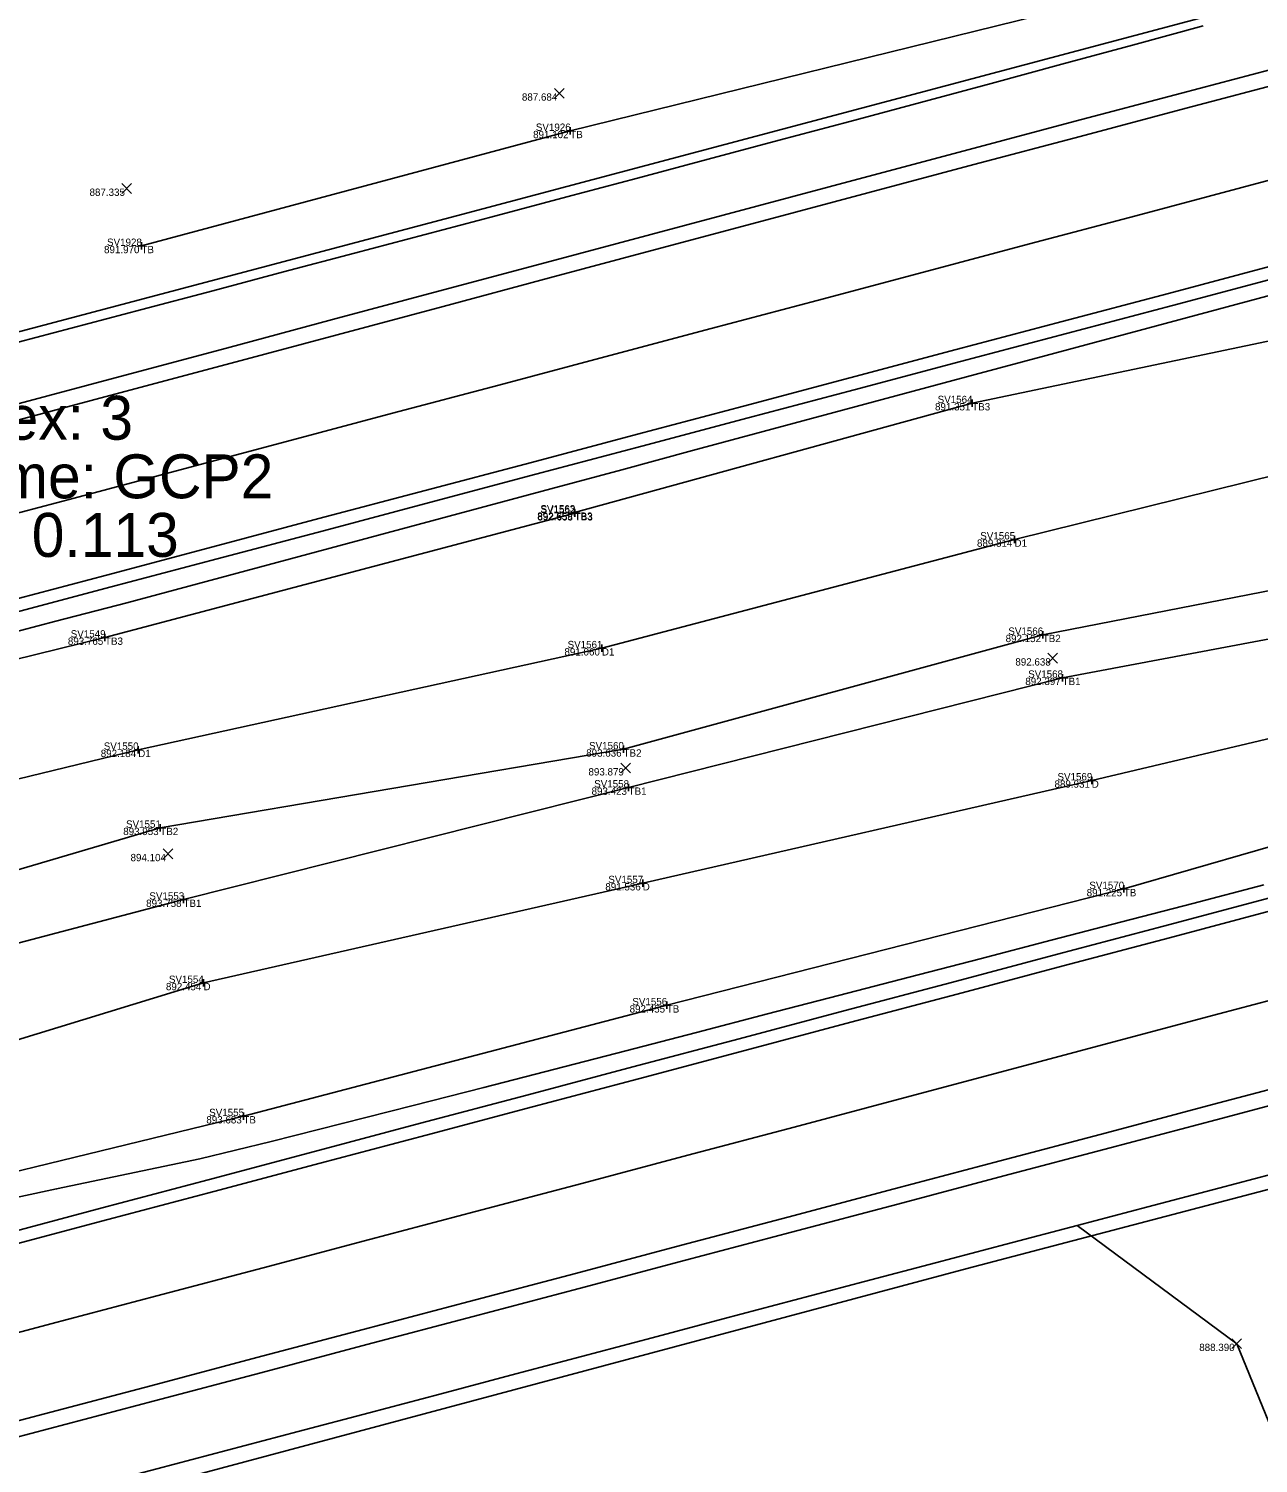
# Model space of a CAD drawing. Extents: x 2125299 to 2129212, y 713100 to 714300.
# Drawn here: x 2127381.3 to 2127549.2, y 713703.4 to 713899.3 of the extents above; entities that cross this region are included whole.
import ezdxf

# ---------------------------------------------------------------- set-up
doc = ezdxf.new("R2010")
doc.units = 0
for name, color, linetype in [('_CIVIL_CONSTRUCTION', 7, 'Continuous'), ('DR_X_Ditch', 7, 'Continuous'), ('DT_X_Terrain_Boundary', 7, 'Continuous'), ('PV_X_EOP', 7, 'Continuous'), ('PV_X_Shoulder_Rumble_Strip', 7, 'Continuous'), ('RW_P_Esmt_TMP', 7, 'Continuous'), ('RW_X_Esmt_CH', 7, 'Continuous'), ('RW_X_Fee_WL', 7, 'Continuous'), ('SC_Scratch1', 7, 'Continuous'), ('SC_Scratch2', 7, 'Continuous'), ('SV_X_Mon_Cells_Found', 7, 'Continuous'), ('SV_X_Text_Elevation', 7, 'Continuous'), ('SV_X_Top_of_Bank', 7, 'Continuous')]:
    doc.layers.add(name, color=color, linetype=linetype)

msp = doc.modelspace()

# ---------------------------------------------------------------- linework, layer by layer
at = {"layer": '_CIVIL_CONSTRUCTION'}
for points in [[(2127372.97, 713831.37), (2127387.47, 713835.22), (2127401.97, 713839.08), (2127416.46, 713842.93), (2127430.96, 713846.79), (2127445.46, 713850.64), (2127459.95, 713854.5), (2127474.45, 713858.35), (2127488.94, 713862.21), (2127503.44, 713866.06), (2127517.94, 713869.92), (2127532.43, 713873.77), (2127546.93, 713877.63), (2127561.42, 713881.48), (2127575.92, 713885.34), (2127590.42, 713889.19), (2127604.91, 713893.05), (2127619.41, 713896.9), (2127633.91, 713900.76), (2127648.4, 713904.61), (2127662.9, 713908.47), (2127677.41, 713912.28)], [(2127369.79, 713718.59), (2127384.29, 713722.43), (2127398.79, 713726.27), (2127413.29, 713730.11), (2127427.79, 713733.95), (2127442.29, 713737.79), (2127456.79, 713741.63), (2127471.29, 713745.47), (2127485.79, 713749.32), (2127500.28, 713753.18), (2127514.78, 713757.04), (2127529.27, 713760.9), (2127543.77, 713764.76), (2127558.26, 713768.62), (2127572.75, 713772.48), (2127587.25, 713776.34), (2127601.74, 713780.2), (2127616.24, 713784.07), (2127630.73, 713787.93), (2127645.23, 713791.77), (2127659.73, 713795.61), (2127674.23, 713799.44)]]:
    msp.add_lwpolyline(points, dxfattribs=at)
at = {"layer": 'DR_X_Ditch'}
for points in [[(2127104.46, 713722.2), (2127161.17, 713739.36), (2127224.94, 713755.07), (2127279.95, 713770.84), (2127341.71, 713787.57), (2127396.23, 713800.84), (2127459.54, 713814.71), (2127515.88, 713829.56), (2127633.42, 713858.63), (2127660.82, 713865.77), (2127680.17, 713870.09), (2127707.74, 713876.68), (2127734.62, 713883.6), (2127780.13, 713896.01), (2127811.25, 713900.24), (2127854.87, 713906.28), (2127890.1, 713912.55), (2127900.96, 713914.65)], [(2127114.72, 713683.53), (2127174.42, 713700.51), (2127233.48, 713715.29), (2127290.34, 713734.33), (2127349.42, 713751.95), (2127405.14, 713769), (2127465.12, 713782.63), (2127526.43, 713796.66), (2127583.18, 713810.08), (2127641.36, 713825.21), (2127649.66, 713823.32), (2127658.57, 713822.87), (2127670.43, 713830.25), (2127710.74, 713841.25), (2127737.15, 713847.1), (2127758.83, 713851.78)]]:
    msp.add_lwpolyline(points, dxfattribs=at)
at = {"layer": 'DT_X_Terrain_Boundary'}
msp.add_lwpolyline([(2127379.41, 713697.54), (2127389.08, 713700.09), (2127398.75, 713702.64), (2127408.42, 713705.18), (2127418.09, 713707.74), (2127427.76, 713710.3), (2127437.42, 713712.86), (2127447.09, 713715.42), (2127456.76, 713717.99), (2127466.42, 713720.55), (2127476.09, 713723.11), (2127485.74, 713725.66), (2127495.42, 713728.23), (2127505.09, 713730.78), (2127514.76, 713733.32), (2127524.43, 713735.87), (2127546.22, 713719.73), (2127560.16, 713685.63), (2127560.57, 713676.96), (2127582.81, 713665.2), (2127597.81, 713640.57), (2127738.64, 713599.23)], dxfattribs=at)
at = {"layer": 'PV_X_EOP'}
for points in [[(2127377.4, 713855.86), (2127387.07, 713858.42), (2127396.74, 713860.98), (2127406.41, 713863.53), (2127416.07, 713866.09), (2127425.74, 713868.64), (2127435.41, 713871.2), (2127445.07, 713873.77), (2127454.74, 713876.35), (2127464.4, 713878.92), (2127474.06, 713881.5), (2127483.73, 713884.07), (2127493.39, 713886.65), (2127503.05, 713889.22), (2127512.7, 713891.83), (2127522.35, 713894.46), (2127532, 713897.08), (2127541.65, 713899.7)], [(2127375.3, 713815.85), (2127384.98, 713818.38), (2127394.65, 713820.92), (2127404.31, 713823.5), (2127413.97, 713826.1), (2127423.62, 713828.7), (2127433.28, 713831.3), (2127442.94, 713833.9), (2127452.59, 713836.49), (2127462.25, 713839.09), (2127471.91, 713841.69), (2127481.56, 713844.29), (2127491.22, 713846.89), (2127500.88, 713849.48), (2127510.53, 713852.08), (2127520.19, 713854.67), (2127529.85, 713857.26), (2127539.51, 713859.86), (2127549.17, 713862.45), (2127558.82, 713865.04)], [(2127375.29, 713738.79), (2127385.08, 713740.86), (2127394.86, 713742.93), (2127404.64, 713745), (2127414.36, 713747.34), (2127424.06, 713749.81), (2127433.75, 713752.27), (2127443.44, 713754.74), (2127453.13, 713757.22), (2127462.8, 713759.73), (2127472.48, 713762.25), (2127482.16, 713764.76), (2127491.84, 713767.28), (2127501.52, 713769.79), (2127511.2, 713772.3), (2127520.88, 713774.82), (2127530.55, 713777.33), (2127540.23, 713779.85), (2127549.91, 713782.38)], [(2127398.75, 713702.64), (2127408.42, 713705.18), (2127418.09, 713707.74), (2127427.76, 713710.3), (2127437.42, 713712.86), (2127447.09, 713715.42), (2127456.76, 713717.99), (2127466.42, 713720.55), (2127476.09, 713723.11), (2127485.76, 713725.67), (2127495.42, 713728.23), (2127505.09, 713730.78), (2127514.76, 713733.32), (2127524.43, 713735.87), (2127534.11, 713738.41), (2127543.78, 713740.96), (2127553.45, 713743.5)]]:
    msp.add_lwpolyline(points, dxfattribs=at)
at = {"layer": 'PV_X_Shoulder_Rumble_Strip'}
for points in [[(2127379.28, 713847.95), (2127393.77, 713851.83), (2127408.26, 713855.7), (2127422.75, 713859.58), (2127437.24, 713863.45), (2127451.73, 713867.33), (2127466.21, 713871.2), (2127480.7, 713875.08), (2127495.19, 713878.95), (2127509.68, 713882.82), (2127524.17, 713886.66), (2127538.67, 713890.5), (2127553.17, 713894.33), (2127567.67, 713898.17), (2127582.17, 713902), (2127596.67, 713905.84), (2127611.16, 713909.67), (2127625.66, 713913.5), (2127640.16, 713917.34), (2127654.66, 713921.17), (2127669.16, 713925.01)], [(2127378.03, 713819.22), (2127392.53, 713823.07), (2127407.02, 713826.92), (2127421.52, 713830.76), (2127436.02, 713834.61), (2127450.51, 713838.46), (2127465.01, 713842.3), (2127479.5, 713846.15), (2127494, 713849.99), (2127508.49, 713853.84), (2127522.99, 713857.69), (2127537.48, 713861.53), (2127551.98, 713865.38), (2127566.47, 713869.23), (2127580.97, 713873.07), (2127595.46, 713876.92), (2127609.96, 713880.76), (2127624.46, 713884.61), (2127638.95, 713888.46), (2127653.45, 713892.3), (2127667.94, 713896.15)], [(2127376.81, 713734.43), (2127391.3, 713738.29), (2127405.79, 713742.13), (2127420.29, 713745.98), (2127434.79, 713749.83), (2127449.28, 713753.68), (2127463.77, 713757.52), (2127478.27, 713761.37), (2127492.76, 713765.22), (2127507.26, 713769.07), (2127521.75, 713772.91), (2127536.25, 713776.76), (2127550.74, 713780.61), (2127565.24, 713784.46), (2127579.73, 713788.3), (2127594.23, 713792.15), (2127608.72, 713796), (2127623.22, 713799.85), (2127637.71, 713803.69), (2127652.21, 713807.54), (2127666.7, 713811.39)], [(2127369.47, 713704.27), (2127383.96, 713708.1), (2127398.46, 713711.94), (2127412.96, 713715.77), (2127427.46, 713719.61), (2127441.96, 713723.44), (2127456.45, 713727.28), (2127470.95, 713731.12), (2127485.45, 713734.96), (2127499.95, 713738.8), (2127514.44, 713742.64), (2127528.94, 713746.48), (2127543.43, 713750.32), (2127557.93, 713754.16), (2127572.43, 713758), (2127586.92, 713761.84), (2127601.42, 713765.68), (2127615.92, 713769.52), (2127630.41, 713773.36), (2127644.91, 713777.2), (2127659.41, 713781.04), (2127673.9, 713784.89)]]:
    msp.add_lwpolyline(points, dxfattribs=at)
at = {"layer": 'SC_Scratch1'}
for points in [[(2127987.17, 714018.86), (2127920.93, 714001.38), (2127683.07, 713938.63), (2127539.5, 713900.27), (2127439.69, 713873.74), (2127381.79, 713858.41), (2127328.47, 713844.31), (2127152.7, 713796.25), (2127072.88, 713773.07)], [(2127133.38, 713627.43), (2127166.26, 713637.18), (2127280.77, 713668.85), (2127395.3, 713699.47), (2127509.42, 713729.99), (2127750.89, 713793.4), (2127929.41, 713841.22)]]:
    msp.add_lwpolyline(points, dxfattribs=at)
at = {"layer": 'SC_Scratch2'}
for points in [[(2127379.92, 713845.89), (2127394.41, 713849.77), (2127408.9, 713853.64), (2127423.39, 713857.52), (2127437.89, 713861.39), (2127452.38, 713865.27), (2127466.87, 713869.14), (2127481.36, 713873.02), (2127495.85, 713876.89), (2127510.34, 713880.77), (2127524.84, 713884.61), (2127539.34, 713888.44), (2127553.84, 713892.28), (2127568.34, 713896.11), (2127582.85, 713899.95), (2127597.35, 713903.79), (2127611.85, 713907.62), (2127626.35, 713911.46), (2127640.85, 713915.29), (2127655.35, 713919.13), (2127669.85, 713922.96)], [(2127377.42, 713820.85), (2127391.91, 713824.7), (2127406.41, 713828.55), (2127420.91, 713832.4), (2127435.41, 713836.24), (2127449.91, 713840.09), (2127464.41, 713843.94), (2127478.9, 713847.78), (2127493.4, 713851.63), (2127507.9, 713855.48), (2127522.4, 713859.32), (2127536.9, 713863.17), (2127551.4, 713867.02), (2127565.89, 713870.86), (2127580.39, 713874.71), (2127594.89, 713878.56), (2127609.39, 713882.41), (2127623.89, 713886.25), (2127638.39, 713890.1), (2127652.88, 713893.95), (2127667.38, 713897.79)], [(2127377.56, 713732.82), (2127392.06, 713736.68), (2127406.56, 713740.53), (2127421.05, 713744.38), (2127435.55, 713748.23), (2127450.05, 713752.07), (2127464.55, 713755.92), (2127479.05, 713759.77), (2127493.54, 713763.62), (2127508.04, 713767.47), (2127522.54, 713771.32), (2127537.04, 713775.16), (2127551.54, 713779.01), (2127566.03, 713782.86), (2127580.53, 713786.71), (2127595.03, 713790.56), (2127609.53, 713794.41), (2127624.03, 713798.25), (2127638.52, 713802.1), (2127653.02, 713805.95), (2127667.52, 713809.8)], [(2127368.93, 713706.32), (2127383.43, 713710.16), (2127397.93, 713713.99), (2127412.43, 713717.83), (2127426.93, 713721.66), (2127441.43, 713725.5), (2127455.93, 713729.34), (2127470.43, 713733.18), (2127484.93, 713737.02), (2127499.43, 713740.86), (2127513.93, 713744.7), (2127528.43, 713748.54), (2127542.93, 713752.38), (2127557.43, 713756.22), (2127571.93, 713760.06), (2127586.43, 713763.9), (2127600.93, 713767.74), (2127615.43, 713771.58), (2127629.93, 713775.43), (2127644.43, 713779.27), (2127658.93, 713783.11), (2127673.43, 713786.96)]]:
    msp.add_lwpolyline(points, dxfattribs=at)
at = {"layer": 'SV_X_Mon_Cells_Found'}
for p, q in [((2127454.72, 713885.36), (2127455.72, 713885.36)), ((2127455.22, 713885.86), (2127455.22, 713884.86)), ((2127455.22, 713885.36), (2127455.22, 713885.36)), ((2127396.17, 713869.65), (2127397.17, 713869.65)), ((2127396.67, 713870.15), (2127396.67, 713869.15)), ((2127396.67, 713869.65), (2127396.67, 713869.65)), ((2127509.61, 713848.18), (2127510.61, 713848.18)), ((2127510.11, 713848.68), (2127510.11, 713847.68)), ((2127510.11, 713848.18), (2127510.11, 713848.18)), ((2127455.8, 713833.75), (2127455.8, 713832.75)), ((2127455.85, 713833.65), (2127455.85, 713832.65)), ((2127455.3, 713833.25), (2127456.3, 713833.25)), ((2127455.35, 713833.15), (2127456.35, 713833.15)), ((2127455.8, 713833.25), (2127455.8, 713833.25)), ((2127455.85, 713833.15), (2127455.85, 713833.15)), ((2127515.88, 713830.06), (2127515.88, 713829.06)), ((2127515.38, 713829.56), (2127516.38, 713829.56)), ((2127515.88, 713829.56), (2127515.88, 713829.56)), ((2127391.19, 713816.17), (2127392.19, 713816.17)), ((2127391.69, 713816.67), (2127391.69, 713815.67)), ((2127391.69, 713816.17), (2127391.69, 713816.17)), ((2127519.24, 713816.54), (2127520.24, 713816.54)), ((2127519.74, 713817.04), (2127519.74, 713816.04)), ((2127519.74, 713816.54), (2127519.74, 713816.54)), ((2127459.04, 713814.71), (2127460.04, 713814.71)), ((2127459.54, 713815.21), (2127459.54, 713814.21)), ((2127459.54, 713814.71), (2127459.54, 713814.71)), ((2127521.95, 713810.68), (2127522.95, 713810.68)), ((2127522.45, 713811.18), (2127522.45, 713810.18)), ((2127522.45, 713810.68), (2127522.45, 713810.68)), ((2127395.73, 713800.84), (2127396.73, 713800.84)), ((2127396.23, 713801.34), (2127396.23, 713800.34)), ((2127396.23, 713800.84), (2127396.23, 713800.84)), ((2127462, 713800.9), (2127463, 713800.9)), ((2127462.5, 713801.4), (2127462.5, 713800.4)), ((2127462.5, 713800.9), (2127462.5, 713800.9)), ((2127525.93, 713796.66), (2127526.93, 713796.66)), ((2127526.43, 713797.16), (2127526.43, 713796.16)), ((2127526.43, 713796.66), (2127526.43, 713796.66)), ((2127462.69, 713795.69), (2127463.69, 713795.69)), ((2127463.19, 713796.19), (2127463.19, 713795.19)), ((2127463.19, 713795.69), (2127463.19, 713795.69)), ((2127399.24, 713790.69), (2127399.24, 713789.69)), ((2127398.74, 713790.19), (2127399.74, 713790.19)), ((2127399.24, 713790.19), (2127399.24, 713790.19)), ((2127464.62, 713782.63), (2127465.62, 713782.63)), ((2127465.12, 713783.13), (2127465.12, 713782.13)), ((2127465.12, 713782.63), (2127465.12, 713782.63)), ((2127402.41, 713780.88), (2127402.41, 713779.88)), ((2127530.31, 713781.83), (2127531.31, 713781.83)), ((2127530.81, 713782.33), (2127530.81, 713781.33)), ((2127530.81, 713781.83), (2127530.81, 713781.83)), ((2127401.91, 713780.38), (2127402.91, 713780.38)), ((2127402.41, 713780.38), (2127402.41, 713780.38)), ((2127404.64, 713769), (2127405.64, 713769)), ((2127405.14, 713769.5), (2127405.14, 713768.5)), ((2127405.14, 713769), (2127405.14, 713769)), ((2127467.9, 713765.95), (2127468.9, 713765.95)), ((2127468.4, 713766.45), (2127468.4, 713765.45)), ((2127468.4, 713765.95), (2127468.4, 713765.95)), ((2127410.59, 713751.31), (2127410.59, 713750.31)), ((2127410.09, 713750.81), (2127411.09, 713750.81)), ((2127410.59, 713750.81), (2127410.59, 713750.81))]:
    msp.add_line(p, q, dxfattribs=at)
at = {"layer": 'SV_X_Text_Elevation'}
for p, q in [((2127453.07, 713889.81), (2127454.41, 713891.15)), ((2127453.07, 713891.15), (2127454.41, 713889.81)), ((2127393.98, 713876.81), (2127395.31, 713878.15)), ((2127393.98, 713878.15), (2127395.31, 713876.81)), ((2127520.43, 713812.68), (2127521.76, 713814.01)), ((2127520.43, 713814.01), (2127521.76, 713812.68)), ((2127462.13, 713797.67), (2127463.46, 713799)), ((2127462.13, 713799), (2127463.46, 713797.67)), ((2127399.63, 713785.96), (2127400.97, 713787.29)), ((2127399.63, 713787.29), (2127400.97, 713785.96)), ((2127545.55, 713719.07), (2127546.89, 713720.4)), ((2127545.55, 713720.4), (2127546.89, 713719.07))]:
    msp.add_line(p, q, dxfattribs=at)
at = {"layer": 'SV_X_Top_of_Bank'}
for points in [[(2127101.4, 713732.92), (2127157.86, 713749.53), (2127222.47, 713767.6), (2127276.61, 713783.01), (2127338.05, 713802.99), (2127391.69, 713816.17), (2127455.85, 713833.15), (2127455.8, 713833.25), (2127510.11, 713848.18), (2127573.33, 713861.42), (2127627.49, 713877.76), (2127656.95, 713884.76), (2127703.68, 713898.62), (2127726.61, 713904.03), (2127772.75, 713915.63), (2127805.28, 713925.94), (2127847.55, 713937.37), (2127886.63, 713945.55), (2127933.44, 713957.72), (2127971.8, 713964.93)], [(2127757.05, 713965.16), (2127696.6, 713949.14), (2127640.68, 713931.02), (2127581.66, 713919.2), (2127522.16, 713901.86), (2127455.22, 713885.36), (2127396.67, 713869.65)], [(2127118.3, 713671.13), (2127177.41, 713689.33), (2127235.14, 713704.98), (2127293.81, 713721.23), (2127351.9, 713736.5), (2127410.59, 713750.81), (2127468.4, 713765.95), (2127530.81, 713781.83), (2127585.7, 713797.67), (2127644.65, 713813.57), (2127714.44, 713829.64), (2127739.44, 713835.61), (2127786.69, 713848.08), (2127820.06, 713857.41), (2127851.23, 713864.33), (2127885.98, 713873.89), (2127912.04, 713881.53)], [(2127107.63, 713707.93), (2127165.88, 713728.25), (2127226.9, 713744.76), (2127282.29, 713761.25), (2127344.58, 713774.07), (2127399.24, 713790.19), (2127462.5, 713800.9), (2127519.74, 713816.54), (2127579.69, 713828.25), (2127636.6, 713845.07), (2127644.25, 713847.13), (2127650.3, 713847.05), (2127656.26, 713844.71)], [(2127109.56, 713700.01), (2127169.1, 713718.64), (2127229.09, 713734.94), (2127284.98, 713752.73), (2127346.09, 713765.57), (2127402.41, 713780.38), (2127463.19, 713795.69), (2127522.45, 713810.68), (2127580.75, 713821.62), (2127638.32, 713836.81), (2127647.09, 713836.55), (2127653.04, 713838.89), (2127656.26, 713844.71)]]:
    msp.add_lwpolyline(points, dxfattribs=at)

# ---------------------------------------------------------------- texts
at = {"layer": '_CIVIL_CONSTRUCTION'}
for s, p in [('Index: 3', (2127366.97, 713843.18)), ('Name: GCP2', (2127366.97, 713835.18)), ('ΔZ: 0.113', (2127366.97, 713827.18))]:
    msp.add_text(s, height=6, dxfattribs=at).set_placement(p)
at = {"layer": 'RW_P_Esmt_TMP'}
for s, p in [('TB', (2127455.22, 713884.36)), ('TB', (2127396.67, 713868.65)), ('TB3', (2127510.11, 713847.18)), ('TB3', (2127455.8, 713832.25)), ('TB3', (2127455.85, 713832.15)), ('D1', (2127515.88, 713828.56)), ('TB3', (2127391.69, 713815.17)), ('TB2', (2127519.74, 713815.54)), ('D1', (2127459.54, 713813.71)), ('TB1', (2127522.45, 713809.68)), ('D1', (2127396.23, 713799.84)), ('TB2', (2127462.5, 713799.9)), ('D', (2127526.43, 713795.66)), ('TB1', (2127463.19, 713794.69)), ('TB2', (2127399.24, 713789.19)), ('D', (2127465.12, 713781.63)), ('TB', (2127530.81, 713780.83)), ('TB1', (2127402.41, 713779.38)), ('D', (2127405.14, 713768)), ('TB', (2127468.4, 713764.95)), ('TB', (2127410.59, 713749.81))]:
    msp.add_text(s, height=1, dxfattribs=at).set_placement(p)
at = {"layer": 'RW_X_Esmt_CH'}
for s, p in [('SV1926', (2127450.52, 713885.36)), ('SV1928', (2127391.97, 713869.65)), ('SV1564', (2127505.39, 713848.18)), ('SV1563', (2127451.14, 713833.25)), ('SV1562', (2127451.18, 713833.15)), ('SV1565', (2127511.21, 713829.56)), ('SV1549', (2127387.01, 713816.17)), ('SV1566', (2127515.04, 713816.54)), ('SV1561', (2127454.86, 713814.71)), ('SV1568', (2127517.75, 713810.68)), ('SV1550', (2127391.52, 713800.84)), ('SV1560', (2127457.79, 713800.9)), ('SV1558', (2127458.49, 713795.69)), ('SV1569', (2127521.75, 713796.66)), ('SV1551', (2127394.56, 713790.19)), ('SV1557', (2127460.42, 713782.63)), ('SV1570', (2127526.1, 713781.83)), ('SV1553', (2127397.75, 713780.38)), ('SV1554', (2127400.42, 713769)), ('SV1556', (2127463.7, 713765.95)), ('SV1555', (2127405.92, 713750.81))]:
    msp.add_text(s, height=1, dxfattribs=at).set_placement(p)
at = {"layer": 'RW_X_Fee_WL'}
for s, p in [('887.684', (2127448.62, 713889.48)), ('891.102', (2127450.15, 713884.36)), ('887.335', (2127389.58, 713876.48)), ('891.970', (2127391.56, 713868.65)), ('891.351', (2127505.03, 713847.18)), ('892.659', (2127450.71, 713832.25)), ('892.658', (2127450.75, 713832.15)), ('889.814', (2127510.76, 713828.56)), ('893.765', (2127386.62, 713815.17)), ('892.152', (2127514.67, 713815.54)), ('891.060', (2127454.43, 713813.71)), ('892.638', (2127516, 713812.34)), ('892.397', (2127517.36, 713809.68)), ('892.184', (2127391.11, 713799.84)), ('893.636', (2127457.4, 713799.9)), ('893.879', (2127457.71, 713797.33)), ('889.931', (2127521.35, 713795.66)), ('893.423', (2127458.13, 713794.69)), ('893.953', (2127394.18, 713789.19)), ('894.104', (2127395.18, 713785.62)), ('891.536', (2127460.01, 713781.63)), ('891.225', (2127525.74, 713780.83)), ('893.758', (2127397.31, 713779.38)), ('892.454', (2127400.01, 713768)), ('892.455', (2127463.33, 713764.95)), ('893.683', (2127405.53, 713749.81)), ('888.390', (2127541.11, 713718.73))]:
    msp.add_text(s, height=1, dxfattribs=at).set_placement(p)

doc.saveas('drawing.dxf')
